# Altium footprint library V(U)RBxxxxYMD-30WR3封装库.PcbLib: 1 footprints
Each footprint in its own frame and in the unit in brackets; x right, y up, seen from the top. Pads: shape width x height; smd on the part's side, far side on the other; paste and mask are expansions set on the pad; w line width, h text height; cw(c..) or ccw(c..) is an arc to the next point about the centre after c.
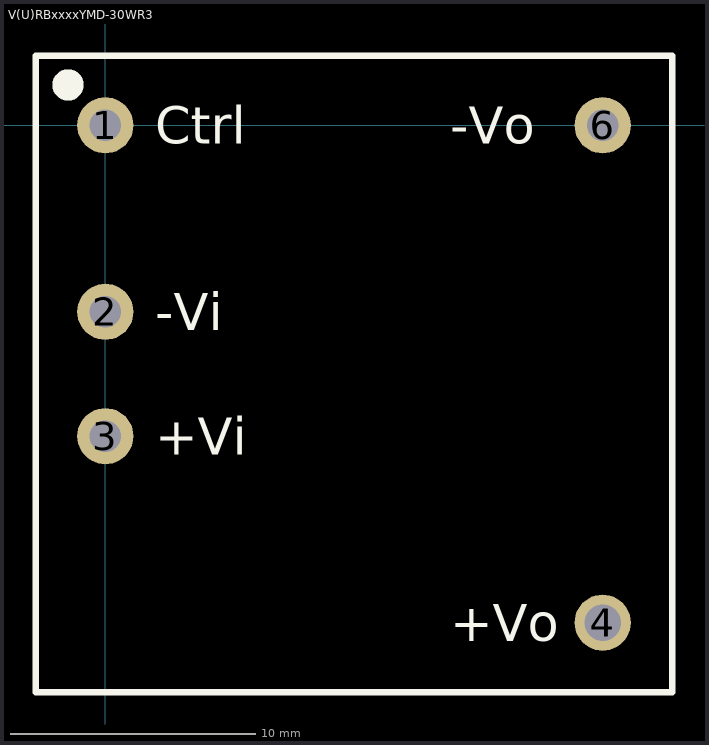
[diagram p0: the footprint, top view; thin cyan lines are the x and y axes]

## V(U)RBxxxxYMD-30WR3 [mm]
pads (5):
  round 2.3 hole 1.3: 1(0,0) 2(0,-7.62) 3(0,-12.7) 6(20.32,0)
  round 2.3 hole 1.5: 4(20.32,-20.32)
Top Overlay:
  circle w0.98: c-1.524,1.651 r0.15
  lines w0.254: -2.84,-23.16 -2.84,2.84 23.16,2.84 23.16,-23.16 -2.84,-23.16
  text "+Vo" at 14.097,-21.082 h1.52
  text "-Vo" at 14.097,-0.762 h1.52
  text "+Vi" at 2.032,-13.462 h1.52
  text "-Vi" at 2.032,-8.382 h1.52
  text "Ctrl" at 2.032,-0.762 h1.52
